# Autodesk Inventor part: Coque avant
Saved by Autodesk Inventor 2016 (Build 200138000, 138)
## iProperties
Created: 2013-08
Part Number: Coque avant
Material: Générique
Document SubType Name: Modeling
Designer: hilarion
Density: 1 g/cm^3
Appearance: Par défaut
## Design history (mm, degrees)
node "Coque avant1"
node "Coque avant"
node "Base1"
